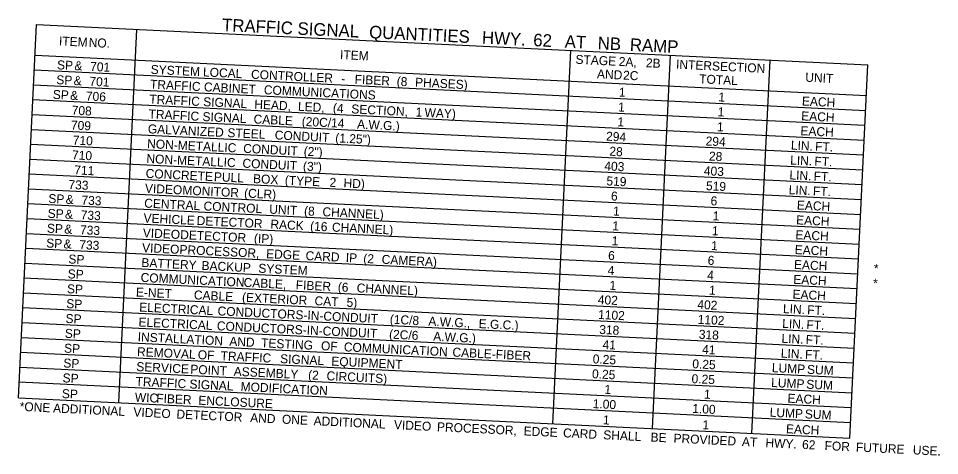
# Model space of a CAD drawing. Extents: x 669100 to 670801, y 741155 to 743955.
# Drawn here: x 669118 to 669374.8, y 743525.6 to 743647.4 of the extents above; entities that cross this region are included whole.
import ezdxf

# ---------------------------------------------------------------- set-up
doc = ezdxf.new("R2010")
doc.units = 0
doc.layers.add('R_Dimension', color=7, linetype='Continuous')

msp = doc.modelspace()

# ---------------------------------------------------------------- linework, layer by layer
at = {"layer": 'R_Dimension'}
for p, q in [((669118.02, 743541.76), (669123.07, 743645.72)), ((669123.07, 743645.72), (669354.85, 743634.46)), ((669146.02, 743540.4), (669151.07, 743644.36)), ((669267.02, 743534.52), (669272.07, 743638.48)), ((669122.66, 743637.2), (669354.43, 743625.94)), ((669294.78, 743533.18), (669299.83, 743637.13)), ((669322.53, 743531.83), (669327.58, 743635.79)), ((669122.46, 743633.06), (669354.23, 743621.8)), ((669349.8, 743530.5), (669354.85, 743634.46)), ((669122.26, 743628.92), (669354.03, 743617.66)), ((669122.05, 743624.78), (669353.83, 743613.52)), ((669121.85, 743620.64), (669353.63, 743609.39)), ((669121.65, 743616.5), (669353.43, 743605.25)), ((669121.45, 743612.36), (669353.23, 743601.11)), ((669121.25, 743608.22), (669353.03, 743596.97)), ((669121.05, 743604.09), (669352.83, 743592.83)), ((669120.85, 743599.95), (669352.63, 743588.69)), ((669120.65, 743595.81), (669352.42, 743584.55)), ((669120.45, 743591.67), (669352.22, 743580.41)), ((669120.25, 743587.53), (669352.02, 743576.27)), ((669120.05, 743583.39), (669351.82, 743572.14)), ((669119.84, 743579.25), (669351.62, 743568)), ((669119.64, 743575.11), (669351.42, 743563.86)), ((669119.44, 743570.97), (669351.22, 743559.72)), ((669119.24, 743566.84), (669351.02, 743555.58)), ((669119.04, 743562.7), (669350.82, 743551.44)), ((669118.84, 743558.56), (669350.62, 743547.3)), ((669118.64, 743554.42), (669350.42, 743543.16)), ((669118.44, 743550.28), (669350.21, 743539.03)), ((669118.24, 743546.14), (669350.01, 743534.89)), ((669118.02, 743541.76), (669349.8, 743530.5))]:
    msp.add_line(p, q, dxfattribs=at)

# ---------------------------------------------------------------- texts
for s, height, p in [('TRAFFIC', 3.5, (669174.73, 743643.91)), (' SIGNAL', 3.5, (669194.47, 743642.95)), (' QUANTITIES', 3.5, (669214.43, 743641.98)), (' HWY.', 3.5, (669245.89, 743640.45)), (' 62', 3.5, (669260.18, 743639.76)), ('ITEM', 2.5, (669129.28, 743639.89)), (' NO.', 2.5, (669136.64, 743639.54)), (' AT', 3.5, (669268.96, 743639.33)), (' NB', 3.5, (669278.15, 743638.89)), (' RAMP', 3.5, (669287.12, 743638.45)), ('ITEM', 2.5, (669207.63, 743636.09)), ('SP', 2.5, (669128.74, 743633.25)), (' &', 2.5, (669132.66, 743633.06)), (' 701', 2.5, (669137.04, 743632.85)), ('STAGE', 2.5, (669273.28, 743634.78)), (' 2A,', 2.5, (669284.41, 743634.24)), (' 2B', 2.5, (669291.98, 743633.87)), ('INTERSECTION', 2.5, (669301.31, 743633.42)), ('SYSTEM', 2.5, (669154.86, 743631.98)), (' LOCAL', 2.5, (669168.51, 743631.32)), (' CONTROLLER', 2.5, (669181.9, 743630.67)), ('AND', 2.5, (669279.27, 743630.73)), (' 2C', 2.5, (669285.62, 743630.42)), ('SP', 2.5, (669128.54, 743629.11)), (' &', 2.5, (669132.46, 743628.92)), (' 701', 2.5, (669136.84, 743628.71)), ('TRAFFIC', 2.5, (669154.66, 743627.85)), (' -', 2.5, (669207.06, 743629.45)), (' FIBER', 2.5, (669210.78, 743629.27)), (' (8', 2.5, (669222.5, 743628.7)), (' PHASES)', 2.5, (669227.63, 743628.45)), ('TOTAL', 2.5, (669307.76, 743629.35)), ('UNIT', 2.5, (669337.34, 743629.79)), ('SP', 2.5, (669127.56, 743625.01)), (' CABINET', 2.5, (669168.76, 743627.16)), (' COMMUNICATIONS', 2.5, (669185.47, 743626.35)), ('1', 2.5, (669285.36, 743625.65)), (' &', 2.5, (669131.48, 743624.82)), (' 706', 2.5, (669135.86, 743624.61)), ('TRAFFIC', 2.5, (669154.46, 743623.71)), (' SIGNAL', 2.5, (669168.56, 743623.02)), (' HEAD,', 2.5, (669182.81, 743622.33)), ('1', 2.5, (669313.11, 743624.3)), ('EACH', 2.5, (669336.4, 743623.17)), ('708', 2.5, (669132.83, 743620.61)), (' LED,', 2.5, (669194.98, 743621.74)), (' (4', 2.5, (669204.72, 743621.27)), (' SECTION,', 2.5, (669209.85, 743621.02)), (' 1', 2.5, (669227.76, 743620.15)), (' WAY)', 2.5, (669230.26, 743620.03)), ('1', 2.5, (669285.16, 743621.51)), ('1', 2.5, (669312.91, 743620.16)), ('TRAFFIC', 2.5, (669154.26, 743619.57)), (' SIGNAL', 2.5, (669168.36, 743618.88)), (' CABLE', 2.5, (669182.61, 743618.19)), (' (20C/14', 2.5, (669196.04, 743617.54)), ('1', 2.5, (669284.96, 743617.37)), ('EACH', 2.5, (669336.2, 743619.03)), ('709', 2.5, (669132.62, 743616.47)), ('GALVANIZED', 2.5, (669154.06, 743615.43)), (' A.W.G.)', 2.5, (669211.47, 743616.79)), ('1', 2.5, (669312.71, 743616.02)), ('EACH', 2.5, (669335.99, 743614.89)), ('710', 2.5, (669133.13, 743612.3)), (' STEEL', 2.5, (669175.31, 743614.4)), (' CONDUIT', 2.5, (669188.51, 743613.76)), (' (1.25")', 2.5, (669205.38, 743612.94)), ('294', 2.5, (669281.81, 743613.37)), ('294', 2.5, (669309.56, 743612.03)), ('NON-METALLIC', 2.5, (669153.86, 743611.29)), (' CONDUIT', 2.5, (669179.71, 743610.03)), ('LIN.', 2.5, (669333.33, 743610.87)), (' FT.', 2.5, (669339.15, 743610.59)), ('710', 2.5, (669132.92, 743608.16)), ('NON-METALLIC', 2.5, (669153.66, 743607.15)), (' (2")', 2.5, (669196.58, 743609.22)), ('28', 2.5, (669282.73, 743609.18)), ('28', 2.5, (669310.48, 743607.83)), (' CONDUIT', 2.5, (669179.51, 743605.9)), (' (3")', 2.5, (669196.38, 743605.08)), ('403', 2.5, (669281.31, 743605.1)), ('LIN.', 2.5, (669333.13, 743606.73)), (' FT.', 2.5, (669338.95, 743606.45)), ('711', 2.5, (669133.54, 743603.98)), ('CONCRETE', 2.5, (669153.45, 743603.01)), (' PULL', 2.5, (669171.54, 743602.13)), ('403', 2.5, (669309.06, 743603.75)), ('LIN.', 2.5, (669332.92, 743602.59)), (' FT.', 2.5, (669338.74, 743602.31)), ('733', 2.5, (669131.92, 743599.91)), (' BOX', 2.5, (669182.46, 743601.6)), (' (TYPE', 2.5, (669191.32, 743601.17)), (' 2', 2.5, (669203.77, 743600.57)), (' HD)', 2.5, (669207.68, 743600.38)), ('519', 2.5, (669281.9, 743600.92)), ('519', 2.5, (669309.66, 743599.58)), ('VIDEO', 2.5, (669153.25, 743598.87)), (' MONITOR', 2.5, (669162.75, 743598.41)), (' (CLR)', 2.5, (669179.97, 743597.58)), ('6', 2.5, (669283.17, 743596.71)), ('LIN.', 2.5, (669332.72, 743598.46)), (' FT.', 2.5, (669338.54, 743598.17)), ('SP', 2.5, (669126.32, 743596.03)), (' &', 2.5, (669130.24, 743595.84)), (' 733', 2.5, (669134.62, 743595.63)), ('CENTRAL', 2.5, (669153.05, 743594.73)), ('6', 2.5, (669310.93, 743595.37)), ('EACH', 2.5, (669334.99, 743594.2)), ('SP', 2.5, (669126.12, 743591.89)), (' &', 2.5, (669130.04, 743591.7)), (' 733', 2.5, (669134.42, 743591.49)), (' CONTROL', 2.5, (669168.66, 743593.98)), (' UNIT', 2.5, (669186.97, 743593.09)), (' (8', 2.5, (669196.68, 743592.62)), (' CHANNEL)', 2.5, (669201.81, 743592.37)), ('1', 2.5, (669283.75, 743592.54)), ('VEHICLE', 2.5, (669152.85, 743590.6)), (' DETECTOR', 2.5, (669166.73, 743589.92)), (' RACK', 2.5, (669187.3, 743588.92)), ('1', 2.5, (669311.5, 743591.19)), ('EACH', 2.5, (669334.79, 743590.06)), ('SP', 2.5, (669125.92, 743587.75)), (' &', 2.5, (669129.84, 743587.56)), (' 733', 2.5, (669134.22, 743587.35)), ('VIDEO', 2.5, (669152.65, 743586.46)), (' (16', 2.5, (669198.37, 743588.39)), (' CHANNEL)', 2.5, (669204.46, 743588.09)), ('1', 2.5, (669283.55, 743588.4)), ('1', 2.5, (669311.3, 743587.05)), (' DETECTOR', 2.5, (669162.15, 743586)), (' (IP)', 2.5, (669182.71, 743585)), ('1', 2.5, (669283.35, 743584.26)), ('EACH', 2.5, (669334.59, 743585.92)), ('SP', 2.5, (669125.72, 743583.62)), (' &', 2.5, (669129.63, 743583.43)), (' 733', 2.5, (669134.02, 743583.21)), ('VIDEO', 2.5, (669152.45, 743582.32)), (' PROCESSOR,', 2.5, (669161.95, 743581.86)), ('1', 2.5, (669311.1, 743582.91)), ('EACH', 2.5, (669334.39, 743581.78)), ('SP', 2.5, (669131.91, 743579.17)), (' EDGE', 2.5, (669186.11, 743580.68)), (' CARD', 2.5, (669197.1, 743580.15)), (' IP', 2.5, (669208.31, 743579.61)), (' (2', 2.5, (669213.19, 743579.37)), (' CAMERA)', 2.5, (669218.32, 743579.12)), ('6', 2.5, (669282.37, 743580.16)), ('6', 2.5, (669310.13, 743578.81)), ('BATTERY', 2.5, (669152.25, 743578.18)), (' BACKUP', 2.5, (669168.1, 743577.41)), (' SYSTEM', 2.5, (669183.94, 743576.64)), ('EACH', 2.5, (669334.19, 743577.64)), ('*', 2.5, (669356.43, 743576.56)), ('SP', 2.5, (669131.71, 743575.03)), ('COMMUNICATION', 2.5, (669152.05, 743574.04)), ('4', 2.5, (669282.24, 743576.02)), ('4', 2.5, (669309.99, 743574.67)), ('EACH', 2.5, (669333.99, 743573.5)), ('SP', 2.5, (669131.51, 743570.89)), (' CABLE,', 2.5, (669179.83, 743572.69)), (' FIBER', 2.5, (669194.36, 743571.99)), (' (6', 2.5, (669206.08, 743571.42)), (' CHANNEL)', 2.5, (669211.35, 743571.16)), ('1', 2.5, (669282.75, 743571.84)), ('*', 2.5, (669356.23, 743572.42)), ('   E-NET', 2.5, (669147.95, 743570.09)), (' CABLE', 2.5, (669165.96, 743569.22)), (' (EXTERIOR', 2.5, (669179.39, 743568.56)), ('1', 2.5, (669310.5, 743570.49)), ('EACH', 2.5, (669333.78, 743569.36)), ('SP', 2.5, (669131.31, 743566.75)), ('ELECTRICAL', 2.5, (669151.65, 743565.76)), (' CAT', 2.5, (669199.6, 743567.58)), (' 5)', 2.5, (669208.53, 743567.15)), ('402', 2.5, (669279.5, 743567.85)), ('402', 2.5, (669307.25, 743566.5)), (' CONDUCTORS-IN-CONDUIT', 2.5, (669172.57, 743564.75)), ('1102', 2.5, (669279.59, 743563.7)), ('LIN.', 2.5, (669331.12, 743565.34)), (' FT.', 2.5, (669336.94, 743565.06)), ('SP', 2.5, (669131.11, 743562.61)), ('ELECTRICAL', 2.5, (669151.45, 743561.62)), (' (1C/8', 2.5, (669220.58, 743562.42)), (' A.W.G.,', 2.5, (669231.34, 743561.89)), (' E.G.C.)', 2.5, (669245.35, 743561.21)), ('1102', 2.5, (669307.35, 743562.35)), ('LIN.', 2.5, (669330.91, 743561.21)), (' FT.', 2.5, (669336.73, 743560.92)), ('SP', 2.5, (669130.91, 743558.47)), (' CONDUCTORS-IN-CONDUIT', 2.5, (669172.37, 743560.61)), (' (2C/6', 2.5, (669220.38, 743558.28)), ('318', 2.5, (669279.9, 743559.53)), ('318', 2.5, (669307.66, 743558.19)), ('INSTALLATION', 2.5, (669151.24, 743557.48)), (' AND', 2.5, (669175.84, 743556.29)), (' TESTING', 2.5, (669184.69, 743555.86)), (' A.W.G.)', 2.5, (669232.69, 743557.68)), ('LIN.', 2.5, (669330.71, 743557.07)), (' FT.', 2.5, (669336.53, 743556.78)), ('SP', 2.5, (669130.71, 743554.33)), ('REMOVAL', 2.5, (669151.04, 743553.35)), (' OF', 2.5, (669201.4, 743555.05)), (' COMMUNICATION', 2.5, (669207.77, 743554.74)), (' CABLE-FIBER', 2.5, (669238.05, 743553.27)), ('41', 2.5, (669280.82, 743555.34)), ('41', 2.5, (669308.58, 743553.99)), ('LIN.', 2.5, (669330.51, 743552.93)), (' OF', 2.5, (669167.05, 743552.57)), (' TRAFFIC', 2.5, (669173.42, 743552.26)), (' SIGNAL', 2.5, (669190.01, 743551.45)), (' EQUIPMENT', 2.5, (669204.27, 743550.76)), ('0.25', 2.5, (669278.08, 743551.33)), (' FT.', 2.5, (669336.33, 743552.65)), ('SP', 2.5, (669130.5, 743550.19)), ('SERVICE', 2.5, (669150.84, 743549.21)), (' POINT', 2.5, (669164.96, 743548.52)), (' ASSEMBLY', 2.5, (669177.07, 743547.93)), ('0.25', 2.5, (669305.84, 743549.98)), ('LUMP', 2.5, (669328.02, 743548.9)), (' SUM', 2.5, (669336.89, 743548.47)), ('SP', 2.5, (669130.3, 743546.06)), (' (2', 2.5, (669197.81, 743546.93)), (' CIRCUITS)', 2.5, (669202.95, 743546.68)), ('0.25', 2.5, (669277.88, 743547.19)), ('0.25', 2.5, (669305.64, 743545.84)), ('TRAFFIC', 2.5, (669150.64, 743545.07)), (' SIGNAL', 2.5, (669164.74, 743544.38)), (' MODIFICATION', 2.5, (669178.99, 743543.69)), ('1', 2.5, (669281.34, 743542.87)), ('LUMP', 2.5, (669327.82, 743544.76)), (' SUM', 2.5, (669336.69, 743544.33)), ('SP', 2.5, (669130.09, 743541.67)), ('WIC', 2.5, (669150.43, 743540.69)), (' FIBER', 2.5, (669155.48, 743540.44)), ('1', 2.5, (669309.09, 743541.52)), ('EACH', 2.5, (669332.38, 743540.39)), ('*ONE', 2.5, (669118.33, 743538.1)), (' ADDITIONAL', 2.5, (669126.71, 743537.69)), (' ENCLOSURE', 2.5, (669167.2, 743539.87)), ('1.00', 2.5, (669278.08, 743538.88)), (' VIDEO', 2.5, (669149.1, 743536.6)), (' DETECTOR', 2.5, (669161.1, 743536.02)), (' AND', 2.5, (669181.66, 743535.02)), ('1.00', 2.5, (669305.83, 743537.53)), ('LUMP', 2.5, (669327.42, 743536.48)), (' SUM', 2.5, (669336.29, 743536.05)), (' ONE', 2.5, (669190.51, 743534.59)), (' ADDITIONAL', 2.5, (669199.34, 743534.16)), (' VIDEO', 2.5, (669221.74, 743533.07)), (' PROCESSOR,', 2.5, (669233.73, 743532.49)), ('1', 2.5, (669280.92, 743534.35)), ('1', 2.5, (669308.68, 743533)), (' EDGE', 2.5, (669257.89, 743531.32)), (' CARD', 2.5, (669268.88, 743530.79)), (' SHALL', 2.5, (669280.09, 743530.24)), ('EACH', 2.5, (669331.96, 743531.87)), (' BE', 2.5, (669293.28, 743529.6)), (' PROVIDED', 2.5, (669299.68, 743529.29)), (' AT', 2.5, (669318.75, 743528.36)), (' HWY.', 2.5, (669325.31, 743528.04)), (' 62', 2.5, (669335.52, 743527.55)), (' FOR', 2.5, (669341.79, 743527.24)), (' FUTURE', 2.5, (669350.52, 743526.82)), (' USE.', 2.5, (669366.39, 743526.05))]:
    msp.add_text(s, height=height, rotation=357.2199, dxfattribs=at).set_placement(p)

doc.saveas('drawing.dxf')
